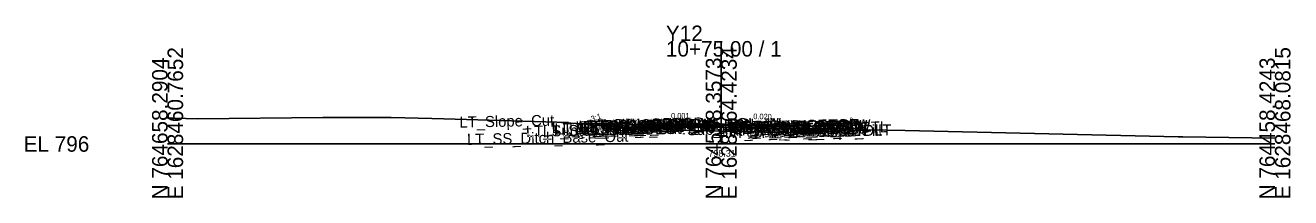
# Model space of a CAD drawing. Extents: x -26 to 203, y -10 to 3521.
# Drawn here: x -25.7 to 202.8, y 1490.3 to 1521.4 of the extents above; entities that cross this region are included whole.
import ezdxf

# ---------------------------------------------------------------- set-up
doc = ezdxf.new("R2010")
doc.units = 0
for name, color, linetype in [('Default', 7, 'Continuous'), ('Exist Cross Section Cell', 7, 'Continuous'), ('Exist XS Center Line Elevation Label', 7, 'Continuous'), ('Exist XS Ground Line', 7, 'Continuous'), ('Prop CMT Conc Surface', 7, 'Continuous'), ('Prop CMT Concrete Structures', 7, 'Continuous'), ('Prop CMT Pvmt Course 1', 7, 'Continuous'), ('Prop CMT Pvmt Course 1 Wedge', 7, 'Continuous'), ('Prop CMT Pvmt Course 2', 7, 'Continuous'), ('Prop CMT Pvmt Course 2 Wedge', 7, 'Continuous'), ('Prop CMT Pvmt Course 3', 7, 'Continuous'), ('Prop CMT Pvmt Course 3 Wedge', 7, 'Continuous'), ('Prop CMT Pvmt Surface', 7, 'Continuous'), ('Prop CMT Pvmt Wedge Surface 1', 7, 'Continuous'), ('Prop CMT Pvmt Wedge Surface 2', 7, 'Continuous'), ('Prop CMT Pvmt Wedge Surface 3', 7, 'Continuous'), ('Prop CMT Shld Paved Course 3', 7, 'Continuous'), ('Prop CMT Slope Grass', 7, 'Continuous'), ('Prop CMT Subgrade Earthwork', 7, 'Continuous'), ('Prop XS SE Text', 7, 'Continuous'), ('Prop XS Side Slope Text', 7, 'Continuous'), ('Scratch_Level_0', 7, 'Continuous')]:
    doc.layers.add(name, color=color, linetype=linetype)

msp = doc.modelspace()

# ---------------------------------------------------------------- linework, layer by layer
at = {"layer": 'Exist Cross Section Cell'}
for p, q in [((100, 1500), (100, 1518.58)), ((0, 1500), (100, 1500)), ((100, 1500), (200, 1500))]:
    msp.add_line(p, q, dxfattribs=at)
at = {"layer": 'Exist XS Ground Line'}
msp.add_lwpolyline([(0, 1504.65), (1.13, 1504.65), (5.45, 1504.55), (28.04, 1504.78), (40.39, 1504.78), (47.73, 1504.62), (49.87, 1504.56), (51.92, 1504.47), (70.31, 1503.96), (76.28, 1503.54), (86.25, 1502.64), (100, 1502.31), (104.83, 1502.19), (113.91, 1502), (116.72, 1502.09), (126.8, 1502.58), (133.21, 1502.44), (182.52, 1501.29), (183.39, 1501.28), (200, 1501.08)], dxfattribs=at)
at = {"layer": 'Prop CMT Conc Surface'}
for points in [[(85, 1503.59), (84, 1503.51), (83, 1503.59)], [(115, 1503.31), (116, 1503.22), (117, 1503.31)]]:
    msp.add_lwpolyline(points, dxfattribs=at)
at = {"layer": 'Prop CMT Concrete Structures'}
for points in [[(85, 1503.59), (84, 1503.51), (83, 1503.59)], [(83, 1503.59), (83, 1503.01)], [(83, 1503.01), (85, 1503.01)], [(85, 1503.01), (85, 1503.59)], [(115, 1503.31), (116, 1503.22), (117, 1503.31)], [(115, 1502.72), (115, 1503.31)], [(117, 1502.72), (115, 1502.72)], [(117, 1503.31), (117, 1502.72)]]:
    msp.add_lwpolyline(points, dxfattribs=at)
at = {"layer": 'Prop CMT Pvmt Course 1'}
for points in [[(100, 1503.61), (85, 1503.59)], [(85, 1503.59), (85, 1503.34)], [(85, 1503.34), (100, 1503.36)], [(100, 1503.61), (86.25, 1503.59)], [(86.25, 1503.59), (86.25, 1503.47)], [(86.25, 1503.47), (100, 1503.48)], [(100, 1503.48), (100, 1503.61)], [(100, 1503.36), (100, 1503.61)], [(100, 1503.61), (113.91, 1503.33)], [(100, 1503.48), (100, 1503.61)], [(100, 1503.61), (115, 1503.31)], [(100, 1503.36), (100, 1503.61)], [(113.91, 1503.2), (100, 1503.48)], [(115, 1503.06), (100, 1503.36)], [(113.91, 1503.33), (113.91, 1503.2)], [(115, 1503.31), (115, 1503.06)]]:
    msp.add_lwpolyline(points, dxfattribs=at)
at = {"layer": 'Prop CMT Pvmt Course 1 Wedge'}
for points in [[(86.25, 1503.47), (100, 1503.48)], [(86.25, 1503.34), (86.25, 1503.47)], [(100, 1503.36), (86.25, 1503.34)], [(100, 1503.48), (100, 1503.36)], [(100, 1503.48), (104.83, 1503.39), (113.91, 1503.2)], [(100, 1503.36), (100, 1503.48)], [(113.91, 1503.08), (104.83, 1503.26), (100, 1503.36)], [(113.91, 1503.2), (113.91, 1503.08), (113.91, 1503.08)]]:
    msp.add_lwpolyline(points, dxfattribs=at)
at = {"layer": 'Prop CMT Pvmt Course 2'}
for points in [[(100, 1503.36), (85, 1503.34)], [(85, 1503.34), (85, 1503.01)], [(85, 1503.01), (100, 1503.02)], [(100, 1503.02), (100, 1503.36)], [(100, 1503.02), (100, 1503.36)], [(100, 1503.36), (115, 1503.06)], [(115, 1502.72), (100, 1503.02)], [(115, 1503.06), (115, 1502.72)]]:
    msp.add_lwpolyline(points, dxfattribs=at)
at = {"layer": 'Prop CMT Pvmt Course 2 Wedge'}
for points in [[(86.25, 1503.34), (100, 1503.36)], [(86.25, 1503.01), (86.25, 1503.34)], [(100, 1503.02), (86.25, 1503.01)], [(100, 1503.36), (100, 1503.02)], [(100, 1503.36), (104.83, 1503.26), (113.91, 1503.08)], [(100, 1503.02), (100, 1503.36)], [(113.91, 1502.75), (104.83, 1502.93), (100, 1503.02)], [(113.91, 1503.08), (113.91, 1502.75), (113.91, 1502.75)]]:
    msp.add_lwpolyline(points, dxfattribs=at)
at = {"layer": 'Prop CMT Pvmt Course 3'}
msp.add_line((117, 1502.72), (117.5, 1502.72), dxfattribs=at)
for points in [[(100, 1503.02), (85, 1503.01)], [(85, 1503.01), (85, 1502.67)], [(85, 1502.67), (86.25, 1502.67)], [(100, 1502.69), (100, 1503.02)], [(100, 1503.02), (115, 1502.72)], [(100, 1502.69), (100, 1503.02)], [(115, 1502.39), (113.91, 1502.41)], [(115, 1502.72), (115, 1502.39)]]:
    msp.add_lwpolyline(points, dxfattribs=at)
at = {"layer": 'Prop CMT Pvmt Course 3 Wedge'}
for points in [[(86.25, 1503.01), (100, 1503.02)], [(86.25, 1502.64), (86.25, 1503.01)], [(100, 1502.31), (86.25, 1502.64)], [(100, 1503.02), (100, 1502.31)], [(100, 1503.02), (104.83, 1502.93), (113.91, 1502.75)], [(100, 1502.31), (100, 1503.02)], [(113.91, 1502), (104.83, 1502.19), (100, 1502.31)], [(113.91, 1502.75), (113.91, 1502), (113.91, 1502)]]:
    msp.add_lwpolyline(points, dxfattribs=at)
at = {"layer": 'Prop CMT Pvmt Surface'}
for points in [[(100, 1503.61), (85, 1503.59)], [(100, 1503.61), (86.25, 1503.59)], [(100, 1503.61), (115, 1503.31)], [(100, 1503.61), (113.91, 1503.33)]]:
    msp.add_lwpolyline(points, dxfattribs=at)
at = {"layer": 'Prop CMT Pvmt Wedge Surface 1'}
for points in [[(85, 1503.34), (85, 1503.59)], [(86.25, 1503.47), (86.25, 1503.59)], [(100, 1503.48), (86.25, 1503.47)], [(100, 1503.48), (113.91, 1503.2)], [(113.91, 1503.2), (113.91, 1503.33)], [(115, 1503.06), (115, 1503.31)]]:
    msp.add_lwpolyline(points, dxfattribs=at)
at = {"layer": 'Prop CMT Pvmt Wedge Surface 2'}
for points in [[(85, 1503.34), (85, 1503.59)], [(86.25, 1503.34), (86.25, 1503.59)], [(100, 1503.36), (86.25, 1503.34)], [(100, 1503.36), (100, 1503.61)], [(100, 1503.36), (100, 1503.61)], [(100, 1503.36), (100, 1503.61)], [(100, 1503.36), (100, 1503.61)], [(100, 1503.36), (113.91, 1503.08)], [(113.91, 1503.08), (113.91, 1503.33)], [(115, 1503.06), (115, 1503.31)]]:
    msp.add_lwpolyline(points, dxfattribs=at)
at = {"layer": 'Prop CMT Pvmt Wedge Surface 3'}
for points in [[(85, 1503.01), (85, 1503.59)], [(86.25, 1503.01), (86.25, 1503.59)], [(100, 1503.02), (86.25, 1503.01)], [(100, 1503.02), (100, 1503.61)], [(100, 1503.02), (100, 1503.61)], [(100, 1503.02), (100, 1503.61)], [(100, 1503.02), (100, 1503.61)], [(100, 1503.02), (113.91, 1502.75)], [(113.91, 1502.75), (113.91, 1503.33)], [(115, 1502.72), (115, 1503.31)]]:
    msp.add_lwpolyline(points, dxfattribs=at)
at = {"layer": 'Prop CMT Shld Paved Course 3'}
for p, q in [((82.16, 1502.67), (85, 1502.67)), ((117.84, 1502.38), (115, 1502.39))]:
    msp.add_line(p, q, dxfattribs=at)
for points in [[(85, 1503.01), (83, 1503.01), (82.5, 1503.01), (82.16, 1502.67)], [(115, 1502.72), (117.5, 1502.72), (117.5, 1502.72), (117.84, 1502.38)]]:
    msp.add_lwpolyline(points, dxfattribs=at)
at = {"layer": 'Prop CMT Slope Grass'}
for points in [[(83, 1503.59), (78, 1503.69), (77.27, 1503.45)], [(117, 1503.31), (122, 1503.41), (124.78, 1502.48)]]:
    msp.add_lwpolyline(points, dxfattribs=at)
at = {"layer": 'Prop CMT Subgrade Earthwork'}
for p, q in [((82.16, 1502.67), (81.2, 1503.63)), ((85, 1502.67), (82.16, 1502.67)), ((115, 1502.39), (117.84, 1502.38)), ((117.84, 1502.38), (118.8, 1503.34))]:
    msp.add_line(p, q, dxfattribs=at)
for points in [[(86.25, 1502.67), (85, 1502.67)], [(86.25, 1502.67), (86.25, 1502.64)], [(113.91, 1502.42), (113.9, 1502)], [(113.91, 1502.41), (115, 1502.39)]]:
    msp.add_lwpolyline(points, dxfattribs=at)

# ---------------------------------------------------------------- texts
at = {"layer": 'Default'}
msp.add_text('-', height=0.0001, dxfattribs=at).set_placement((0, 1500))
at = {"layer": 'Exist Cross Section Cell'}
for s, p in [('Y12', (90, 1518.58)), ('10+75.00 / 1', (90, 1515.78)), ('EL 796', (-26, 1498.6))]:
    msp.add_text(s, height=2.8, dxfattribs=at).set_placement(p)
for s, p in [('N 764658.2904', (0, 1490)), ('E 1628460.7652', (2.8, 1490)), ('N 764558.3573', (100, 1490)), ('E 1628464.4234', (102.8, 1490)), ('N 764458.4243', (200, 1490)), ('E 1628468.0815', (202.8, 1490))]:
    msp.add_text(s, height=2.8, rotation=90, dxfattribs=at).set_placement(p)
at = {"layer": 'Exist XS Center Line Elevation Label'}
msp.add_text('798.31', height=1.2, dxfattribs=at).set_placement((97.69, 1497.71))
at = {"layer": 'Prop XS SE Text'}
for s, rotation, p in [('0.001', 0.0674, (90.93, 1504.6)), ('0.020', 358.8542, (105.77, 1504.49))]:
    msp.add_text(s, height=1, rotation=rotation, dxfattribs=at).set_placement(p)
at = {"layer": 'Prop XS Side Slope Text'}
for rotation, p in [(18.4332, (76.65, 1504.03)), (341.5668, (122.88, 1503.91))]:
    msp.add_text('3:1', height=1, rotation=rotation, dxfattribs=at).set_placement(p)
at = {"layer": 'Scratch_Level_0'}
for s, p in [('LT_Slope_Cut', (52.74, 1502.95)), ('LT_Sub_Trench_Out', (67.79, 1501.33)), ('LT_GS_OS_CTL', (69.39, 1501.98)), ('LT_PS3_Shelf_Out', (69.91, 1501.7)), ('LT_PV2_OEEOP_W', (73.69, 1502.09)), ('LT_PV3_OEEOP_W', (73.69, 1501.76)), ('LT_PV1_OEEOP_W', (74.26, 1502.23)), ('LT_PS3_OEOP', (74.66, 1501.8)), ('LT_PS2_OEOP', (75, 1502.14)), ('LT_Sub_OEOT', (75.1, 1501.48)), ('LT_PV2_OEOT', (75.2, 1502.14)), ('LT_PV3_OEOT', (75.2, 1501.81)), ('LT_PV1_OEOT', (75.76, 1502.41)), ('LT_PS1_OEOP', (75.82, 1502.41)), ('LT_PV1_OEEOP', (76.14, 1502.39)), ('RT_PV1_PGL_W', (89.86, 1502.28)), ('LT_PV1_PGL_W', (89.91, 1502.28)), ('Sub_PGL', (93.83, 1501.57)), ('PV2_PGL', (93.93, 1502.24)), ('PV3_PGL', (93.93, 1501.9)), ('PV1_PGL', (94.49, 1502.5)), ('RT_PV2_OEEOP_W', (101.3, 1501.83)), ('RT_PV3_OEEOP_W', (101.3, 1501.49)), ('RT_PV1_OEEOP_W', (101.87, 1501.96)), ('RT_PS3_Shelf_Out', (102.06, 1501.42)), ('RT_PV1_OEEOP', (103.75, 1502.13)), ('RT_PV2_OEOT', (105.15, 1501.86)), ('RT_PV3_OEOT', (105.15, 1501.53)), ('RT_PS2_OEOP', (105.47, 1501.86)), ('RT_PV1_OEOT', (105.71, 1502.12)), ('RT_PS1_OEOP', (105.78, 1502.12)), ('RT_PS3_OEOP', (105.81, 1501.52)), ('RT_GS_OS_CTL', (109.34, 1501.69)), ('LT_SS_Ditch_Base_Out', (54.1, 1499.83)), ('LT_Sub_OSS_DLT', (64.74, 1501.27)), ('RT_Sub_Trench_Out', (100.62, 1501.05)), ('RT_Sub_OEOT', (105.05, 1501.19)), ('RT_Sub_OSS_DLT', (107.27, 1501.08)), ('RT_Slope_Fill', (112.21, 1501.14))]:
    msp.add_text(s, height=2, rotation=1.1458, dxfattribs=at).set_placement(p)

doc.saveas('drawing.dxf')
